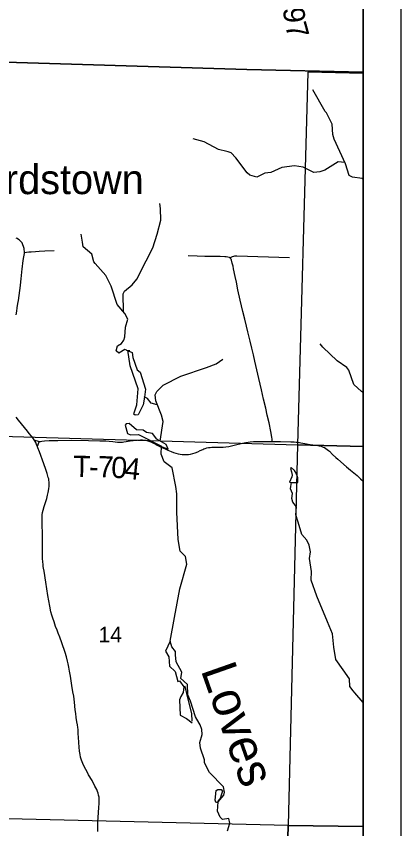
# Model space of a CAD drawing. Extents: x 0 to 34, y 0 to 22.
# Drawn here: x 8.476 to 9.5, y 14.47 to 16.635 of the extents above; entities that cross this region are included whole.
import ezdxf

# ---------------------------------------------------------------- set-up
doc = ezdxf.new("R2010")
doc.units = 0
for name, color, linetype in [('GM_X_Corporation', 7, 'Continuous'), ('GM_X_County', 7, 'Continuous'), ('GM_X_Minor_River', 7, 'Continuous'), ('GM_X_Minor_River_Text', 7, 'Continuous'), ('GM_X_Section_Text', 7, 'Continuous'), ('GM_X_Township_Road', 7, 'Continuous'), ('GM_X_Township_Road_Text', 7, 'Continuous'), ('GM_X_Unincorporated_Text', 7, 'Continuous'), ('SH_Data', 7, 'Continuous')]:
    doc.layers.add(name, color=color, linetype=linetype)

msp = doc.modelspace()

# ---------------------------------------------------------------- linework, layer by layer
at = {"layer": 'GM_X_Corporation'}
for points in [[(9.4, 16.4853), (9.4, 20.4), (2.6, 20.4), (2.6, 16.6918), (3.1555, 16.6686), (3.1684, 16.6682), (4.0515, 16.6368), (4.1011, 16.6362), (4.1867, 16.6352), (4.5473, 16.6256), (4.6351, 16.6229), (5.4202, 16.5982), (6.0834, 16.5816), (6.2194, 16.578), (8.0963, 16.5226), (9.09, 16.4927)], [(9.4, 16.4853), (9.4, 20.4), (6.2895, 20.4), (6.2595, 19.6124), (6.2942, 19.6131), (6.2926, 19.1539), (6.292, 18.5898), (6.2786, 18.5898), (6.2744, 18.4654), (6.2729, 18.2077), (6.2194, 16.578), (8.0963, 16.5226), (9.09, 16.4927)], [(2.6, 16.6918), (2.6, 13.6), (9.4, 13.6), (9.4, 16.4853), (9.09, 16.4927), (8.0963, 16.5226), (6.2194, 16.578), (6.0834, 16.5816), (5.4202, 16.5982), (4.6351, 16.6229), (4.5473, 16.6256), (4.1867, 16.6352), (4.1011, 16.6362), (4.0515, 16.6368), (3.1684, 16.6682), (3.1555, 16.6686)], [(9.4, 15.4882), (9.4, 16.4822), (9.2526, 16.4858), (9.225, 15.4925)], [(9.225, 15.4925), (9.1998, 14.4779), (8.1927, 14.5025), (8.2216, 15.5221)], [(9.4, 14.4754), (9.4, 15.4882), (9.225, 15.4925), (9.1998, 14.4779)], [(8.1659, 13.6), (9.1765, 13.6), (9.1998, 14.4779), (8.1927, 14.5025)], [(9.1765, 13.6), (9.4, 13.6), (9.4, 14.4754), (9.1998, 14.4779)]]:
    msp.add_lwpolyline(points, close=True, dxfattribs=at)
msp.add_lwpolyline([(4.5781, 13.6), (9.4, 13.6), (9.4, 16.4853), (9.09, 16.4927), (8.0963, 16.5226), (6.2194, 16.578), (6.0834, 16.5816), (5.4202, 16.5982), (4.6351, 16.6229)], dxfattribs=at)
at = {"layer": 'GM_X_County'}
msp.add_lwpolyline([(9.4, 16.4853), (9.09, 16.4927), (8.0963, 16.5226), (6.2194, 16.578), (6.0834, 16.5816), (5.4202, 16.5982), (4.6351, 16.6229), (4.5473, 16.6256), (4.1867, 16.6352), (4.1011, 16.6362), (4.0515, 16.6368), (3.1684, 16.6682), (3.1555, 16.6686), (2.6, 16.6918)], dxfattribs=at)
at = {"layer": 'GM_X_Minor_River'}
for points in [[(9.4, 16.1998), (9.397, 16.2019), (9.3711, 16.2059), (9.3622, 16.2102), (9.3528, 16.2414), (9.3228, 16.307), (9.3187, 16.3194), (9.3177, 16.3466), (9.3022, 16.3769), (9.2991, 16.381), (9.2655, 16.4381)], [(9.3511, 16.245), (9.3333, 16.247), (9.2981, 16.2242), (9.2842, 16.2197), (9.2687, 16.2179), (9.2403, 16.232), (9.217, 16.2356), (9.1833, 16.2318), (9.1544, 16.2182), (9.1381, 16.2163), (9.1163, 16.2056), (9.098, 16.2108), (9.0907, 16.2171), (9.0605, 16.2576), (9.0481, 16.2702), (9.0404, 16.2735), (9.0366, 16.2745), (9.0148, 16.2797), (8.9768, 16.3), (8.947, 16.3076)], [(8.7611, 15.8476), (8.7602, 15.8946), (8.7646, 15.9023), (8.7847, 15.919), (8.7973, 15.9341), (8.8216, 15.9828), (8.8398, 16.0173), (8.8511, 16.0543), (8.8608, 16.0913), (8.8605, 16.1219), (8.8587, 16.1355)], [(8.7697, 15.7452), (8.7651, 15.7462), (8.7494, 15.7364), (8.7417, 15.743), (8.7455, 15.7563), (8.756, 15.763), (8.7623, 15.7711), (8.7655, 15.7803), (8.7668, 15.8057), (8.7735, 15.8278), (8.7652, 15.8428), (8.7445, 15.8669), (8.7286, 15.9158), (8.7147, 15.9439), (8.6858, 15.9762), (8.6827, 15.9799), (8.6773, 16.0002), (8.6545, 16.0201), (8.6523, 16.0322), (8.6491, 16.0541)], [(9.4, 15.6323), (9.3955, 15.6351), (9.375, 15.6536), (9.3616, 15.6912), (9.3561, 15.6986), (9.331, 15.7162), (9.2926, 15.7532), (9.2852, 15.7618)], [(8.7697, 15.7452), (8.7781, 15.7439)], [(8.7697, 15.7452), (8.7843, 15.7387), (8.7861, 15.7251), (8.7979, 15.6924), (8.8056, 15.6858), (8.8203, 15.641), (8.8173, 15.6198)], [(8.8173, 15.6198), (8.8141, 15.5992), (8.801, 15.5724), (8.7927, 15.5718), (8.7888, 15.5744), (8.7895, 15.5782), (8.7966, 15.5992), (8.8005, 15.6421), (8.7794, 15.703), (8.7735, 15.7446)], [(8.8596, 15.5027), (8.8671, 15.5546), (8.8625, 15.5716), (8.8472, 15.6098), (8.8461, 15.6261), (8.8504, 15.6349), (8.8668, 15.6512), (8.914, 15.6758), (8.983, 15.6983), (9.0086, 15.7087), (9.0257, 15.7209)], [(8.8515, 15.5991), (8.8356, 15.6039), (8.8258, 15.6162), (8.8166, 15.6201)], [(8.8629, 15.4886), (8.8805, 15.481), (8.8753, 15.4934), (8.8507, 15.508), (8.8386, 15.5229), (8.8226, 15.5259), (8.8141, 15.5318), (8.7962, 15.5325), (8.7769, 15.5491), (8.7689, 15.5489), (8.7663, 15.5447), (8.7721, 15.5228), (8.7806, 15.5188), (8.8014, 15.5201), (8.8629, 15.489)], [(8.8862, 14.9695), (8.8973, 15.0327), (8.9115, 15.1092), (8.9304, 15.1748), (8.9266, 15.1948), (8.9126, 15.2089), (8.9069, 15.2402), (8.9037, 15.3133), (8.9038, 15.3622), (8.901, 15.3818), (8.8915, 15.4316), (8.8699, 15.4474), (8.8622, 15.4673), (8.8629, 15.489)], [(9.2092, 15.3923), (9.2257, 15.3924), (9.2262, 15.4046), (9.2217, 15.4174), (9.217, 15.4245), (9.2085, 15.4318), (9.2063, 15.4299), (9.2091, 15.4205), (9.2109, 15.4114), (9.2102, 15.4069), (9.2033, 15.3927), (9.2092, 15.3923)], [(9.4, 14.8057), (9.3775, 14.8319), (9.3732, 14.8367), (9.3646, 14.8487), (9.3634, 14.8691), (9.3465, 14.893), (9.3269, 14.9206), (9.3219, 14.9535), (9.3181, 14.989), (9.3048, 15.0209), (9.2767, 15.0896), (9.2617, 15.1317), (9.2619, 15.1553), (9.2569, 15.1893), (9.2599, 15.2079), (9.2574, 15.2207), (9.2561, 15.2249), (9.2501, 15.2384), (9.2369, 15.254), (9.2266, 15.2863), (9.2209, 15.3063), (9.2219, 15.3275), (9.2129, 15.3398), (9.21, 15.3493), (9.2116, 15.3633), (9.2064, 15.3753), (9.2094, 15.3932)], [(8.8862, 14.9695), (8.8731, 14.9427), (8.8826, 14.9281), (8.8839, 14.9031), (8.899, 14.8883), (8.9065, 14.8623), (8.9106, 14.8639), (8.9224, 14.8475)], [(8.9143, 14.8701), (8.9169, 14.8868), (8.9015, 14.9145), (8.9003, 14.9327), (8.9001, 14.9418), (8.89, 14.954), (8.8862, 14.9695)], [(9.0382, 14.4639), (9.045, 14.4846), (9.042, 14.4966), (9.0254, 14.4947), (9.0192, 14.5003), (9.0123, 14.5164), (9.0133, 14.5414), (9.0284, 14.5592), (9.0305, 14.5669), (9.0283, 14.5812), (8.991, 14.6198), (8.9775, 14.6449), (8.9773, 14.6532), (8.9664, 14.6844), (8.9652, 14.6996), (8.9708, 14.7209), (8.9701, 14.7345), (8.9653, 14.7469), (8.9629, 14.7507), (8.9534, 14.7679), (8.94, 14.8093), (8.9327, 14.8269), (8.9321, 14.8538), (8.9131, 14.8712)], [(8.9442, 14.7567), (8.9434, 14.7764), (8.9338, 14.8148), (8.9261, 14.8488), (8.9224, 14.8475), (8.9201, 14.8331), (8.9142, 14.8216), (8.9106, 14.8131), (8.9123, 14.7726), (8.9289, 14.7635), (8.9447, 14.7518)], [(9.0132, 14.5384), (9.0076, 14.5406), (9.0056, 14.5454), (9.008, 14.5713), (9.0129, 14.5744), (9.022, 14.5743), (9.0252, 14.5698), (9.0223, 14.5614), (9.0188, 14.5499), (9.0121, 14.5422)]]:
    msp.add_lwpolyline(points, dxfattribs=at)
at = {"layer": 'GM_X_Township_Road'}
for points in [[(8.4757, 15.839), (8.4771, 15.8484), (8.4786, 15.8578), (8.4801, 15.869), (8.4815, 15.8773), (8.4868, 15.9174), (8.4891, 15.9359), (8.4897, 15.9425), (8.4907, 15.9537), (8.4914, 15.9605), (8.4923, 15.9689), (8.4934, 15.976), (8.4945, 15.9838), (8.496, 15.9933), (8.4974, 16.0028), (8.4976, 16.0052), (8.4969, 16.0157), (8.4954, 16.0209), (8.4936, 16.0257), (8.4923, 16.0286), (8.4912, 16.0306), (8.4891, 16.0333), (8.4844, 16.0377), (8.4822, 16.0394), (8.478, 16.0421), (8.4752, 16.0437)], [(8.4976, 16.0052), (8.5029, 16.0058), (8.5094, 16.0066), (8.5157, 16.0071), (8.5268, 16.0079), (8.5366, 16.0085), (8.5523, 16.0092), (8.5767, 16.0104)], [(8.9341, 15.9972), (8.9579, 15.9962), (8.9781, 15.9954), (9.002, 15.9952), (9.0191, 15.9949), (9.0316, 15.9945), (9.0351, 15.9942), (9.0395, 15.9934), (9.0429, 15.9924), (9.0449, 15.9911), (9.0498, 15.9938), (9.0522, 15.9948), (9.0552, 15.9956), (9.0578, 15.996), (9.0634, 15.9965), (9.2036, 15.9914)], [(9.1576, 15.5019), (9.1574, 15.5074), (9.1568, 15.5134), (9.1542, 15.528), (9.1492, 15.5508), (9.1445, 15.5713), (9.1402, 15.5903), (9.1346, 15.6139), (9.1287, 15.6394), (9.1219, 15.6697), (9.1167, 15.6924), (9.1113, 15.7157), (9.1077, 15.7322), (9.1036, 15.7506), (9.0992, 15.7687), (9.093, 15.7937), (9.0894, 15.8088), (9.0849, 15.8273), (9.0794, 15.8483), (9.0726, 15.8784), (9.0665, 15.9058), (9.0621, 15.926), (9.0589, 15.9413), (9.0549, 15.9613), (9.0532, 15.9688), (9.0514, 15.9764), (9.0492, 15.9844), (9.0481, 15.9871), (9.0466, 15.9894), (9.0449, 15.9911)], [(8.5237, 15.5058), (8.5197, 15.5111), (8.5166, 15.5154), (8.5103, 15.5232), (8.5057, 15.5289), (8.482, 15.5582), (8.4752, 15.5664)], [(8.6928, 14.4625), (8.6929, 14.4794), (8.6931, 14.4883), (8.6938, 14.4993), (8.6948, 14.5127), (8.6961, 14.5261), (8.6966, 14.5369), (8.6968, 14.5453), (8.6963, 14.554), (8.6953, 14.559), (8.6937, 14.5649), (8.6922, 14.5691), (8.6901, 14.5742), (8.6856, 14.5829), (8.6777, 14.5979), (8.6686, 14.6135), (8.6644, 14.621), (8.6579, 14.6341), (8.6532, 14.6439), (8.6498, 14.6526), (8.6473, 14.6606), (8.6458, 14.6673), (8.6445, 14.6762), (8.6431, 14.6869), (8.6423, 14.6992), (8.6416, 14.7137), (8.6412, 14.7225), (8.6405, 14.7339), (8.64, 14.7394), (8.639, 14.7463), (8.6375, 14.7543), (8.6356, 14.7665), (8.6344, 14.7765), (8.633, 14.7866), (8.6311, 14.8067), (8.6289, 14.8229), (8.6269, 14.8349), (8.6241, 14.8517), (8.62, 14.876), (8.6181, 14.8891), (8.6161, 14.8999), (8.6141, 14.9095), (8.6126, 14.9158), (8.6094, 14.9276), (8.6057, 14.9389), (8.5973, 14.9646), (8.5917, 14.9799), (8.5873, 14.9906), (8.5844, 14.9988), (8.5808, 15.0088), (8.5767, 15.0212), (8.5733, 15.0308), (8.5709, 15.0386), (8.5681, 15.048), (8.5653, 15.0625), (8.5604, 15.0914), (8.555, 15.1263), (8.5498, 15.1558), (8.5485, 15.1641), (8.5477, 15.1684), (8.5471, 15.1743), (8.5466, 15.1804), (8.5461, 15.1905), (8.5462, 15.2217), (8.5461, 15.2484), (8.5458, 15.2604), (8.5452, 15.2748), (8.5448, 15.2823), (8.5446, 15.2953), (8.5449, 15.3008), (8.5453, 15.3061), (8.5462, 15.312), (8.5475, 15.3181), (8.5502, 15.328), (8.5569, 15.35), (8.5593, 15.3584), (8.5609, 15.3652), (8.5621, 15.3704), (8.563, 15.376), (8.5636, 15.3814), (8.5639, 15.3877), (8.5637, 15.3932), (8.563, 15.3984), (8.5624, 15.4018), (8.5612, 15.406), (8.5579, 15.4166), (8.5543, 15.4269), (8.5491, 15.4416), (8.5374, 15.4737), (8.5336, 15.4843), (8.5323, 15.4876), (8.53, 15.4932), (8.5276, 15.4987), (8.5251, 15.5034), (8.5237, 15.5058)], [(8.5237, 15.5058), (8.5279, 15.5042), (8.5313, 15.5033), (8.5346, 15.5023), (8.538, 15.5015)], [(8.5323, 15.4876), (8.5332, 15.4912), (8.5341, 15.4938), (8.5351, 15.4962), (8.5361, 15.4984), (8.538, 15.5015), (8.54, 15.5019), (8.5439, 15.5027), (8.5512, 15.5034), (8.5631, 15.5039), (8.587, 15.5045), (8.6241, 15.5048), (8.6686, 15.5044), (8.6986, 15.5036), (8.7147, 15.5029), (8.7231, 15.5024), (8.7333, 15.5014), (8.7455, 15.4999), (8.7509, 15.4995), (8.7587, 15.4998), (8.762, 15.5002), (8.7688, 15.5013), (8.7794, 15.5031), (8.7873, 15.5042), (8.7975, 15.5051), (8.8065, 15.5056), (8.812, 15.5055), (8.8164, 15.5052), (8.8205, 15.5046), (8.8264, 15.5033), (8.8314, 15.5016), (8.8344, 15.5005), (8.8396, 15.498), (8.8456, 15.495), (8.8516, 15.4916), (8.8618, 15.4867), (8.8725, 15.4815), (8.8796, 15.4783), (8.8883, 15.4747), (8.8946, 15.4724), (8.901, 15.4701), (8.9071, 15.4683), (8.9121, 15.4675), (8.9174, 15.4669), (8.9226, 15.4665), (8.9347, 15.4672), (8.9404, 15.4681), (8.9458, 15.4694), (8.9525, 15.4717), (8.9593, 15.4743), (8.966, 15.4772), (8.9727, 15.4801), (8.9757, 15.4816), (8.9794, 15.4831), (8.9832, 15.4843), (8.9882, 15.4852), (8.9922, 15.4856), (8.9967, 15.486), (9.0093, 15.4861), (9.0192, 15.4864), (9.0268, 15.4866), (9.0343, 15.4872), (9.0417, 15.4884), (9.0563, 15.4914), (9.0786, 15.4968), (9.0872, 15.4987), (9.0934, 15.4999), (9.0985, 15.5007), (9.1078, 15.5015), (9.1168, 15.5017), (9.1321, 15.5018), (9.148, 15.5019), (9.1576, 15.5019), (9.1643, 15.5017), (9.1801, 15.5013), (9.2069, 15.501), (9.2159, 15.5006), (9.2215, 15.4999), (9.2264, 15.4993), (9.2341, 15.4979), (9.2442, 15.496), (9.2536, 15.4945), (9.2588, 15.4936), (9.2662, 15.4926), (9.2744, 15.4916), (9.2823, 15.4902), (9.2858, 15.4895), (9.2899, 15.4883), (9.2937, 15.4868), (9.2965, 15.4854), (9.3009, 15.4826), (9.3041, 15.4803), (9.3077, 15.4775), (9.3099, 15.4755), (9.3184, 15.4672), (9.3273, 15.4586), (9.332, 15.4543), (9.3557, 15.4342), (9.3661, 15.4255), (9.3836, 15.4107), (9.3895, 15.4054), (9.3932, 15.4021), (9.4, 15.3962)]]:
    msp.add_lwpolyline(points, dxfattribs=at)
at = {"layer": 'SH_Data'}
for points in [[(2.5, 20.5), (9.5, 20.5), (9.5, 13.5), (2.5, 13.5)], [(2.6, 20.4), (9.4, 20.4), (9.4, 13.6), (2.6, 13.6)]]:
    msp.add_lwpolyline(points, close=True, dxfattribs=at)

# ---------------------------------------------------------------- texts
at = {"layer": 'GM_X_Minor_River_Text'}
msp.add_text('Loves', height=0.09462, rotation=289.3644, dxfattribs=at).set_placement((8.9667, 14.8926))
at = {"layer": 'GM_X_Section_Text'}
msp.add_text('14', height=0.04186, rotation=0, dxfattribs=at).set_placement((8.695, 14.966))
at = {"layer": 'GM_X_Township_Road_Text'}
for s, rotation, p in [('9', 274.9285, (9.1863, 16.6565)), ('7', 285.4305, (9.1913, 16.6104)), ('T', 359.1129, (8.6272, 15.407)), ('7', 358.8967, (8.693, 15.406)), ('0', 356.4227, (8.7274, 15.4053)), ('4', 353.9523, (8.7616, 15.4032)), ('-', 359.0788, (8.6697, 15.4063))]:
    msp.add_text(s, height=0.0568, rotation=rotation, dxfattribs=at).set_placement(p)
at = {"layer": 'GM_X_Unincorporated_Text'}
msp.add_text('Shepherdstown', height=0.078977, rotation=0, dxfattribs=at).set_placement((8.0816, 16.1606))

doc.saveas('drawing.dxf')
